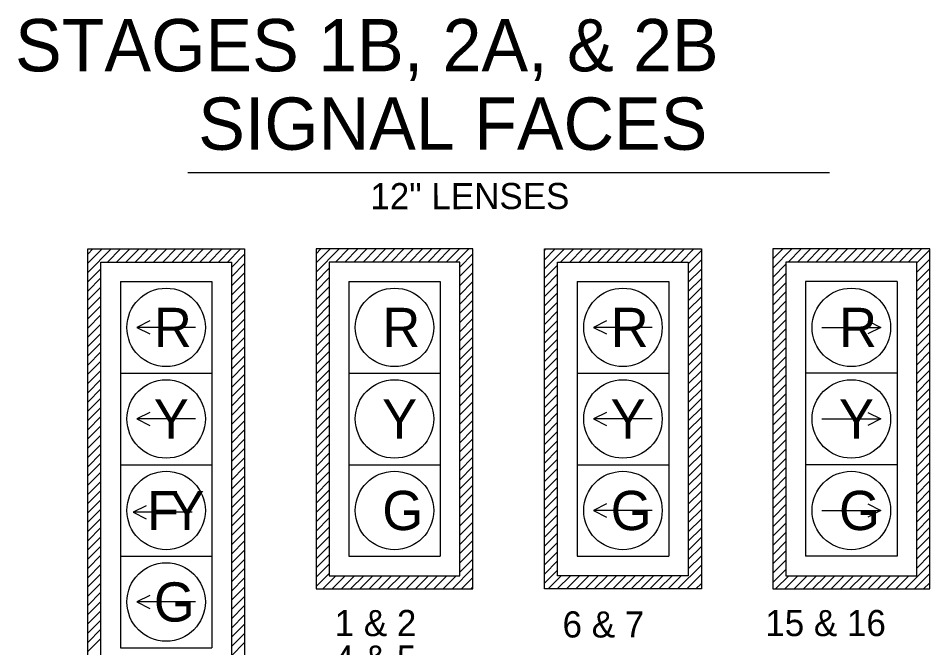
# Model space of a CAD drawing. Extents: x -218554 to 420030, y -566264 to -483460.
# Drawn here: x 419069.9 to 419209.4, y -565377 to -565280.7 of the extents above; entities that cross this region are included whole.
import ezdxf

# ---------------------------------------------------------------- set-up
doc = ezdxf.new("R2010")
doc.units = 0
doc.layers.add('T_Drafting', color=7, linetype='Continuous')
doc.layers.add('T_Notes', color=7, linetype='Continuous')

msp = doc.modelspace()

# ---------------------------------------------------------------- linework, layer by layer
at = {"layer": 'T_Drafting'}
for p, q in [((419080.56, -565381.97), (419080.56, -565315.97)), ((419080.56, -565315.97), (419104.56, -565315.97)), ((419080.56, -565319.58), (419084.16, -565315.97)), ((419080.56, -565318.16), (419082.75, -565315.97)), ((419080.56, -565316.75), (419081.33, -565315.97)), ((419083.58, -565317.97), (419085.58, -565315.97)), ((419084.99, -565317.97), (419086.99, -565315.97)), ((419086.41, -565317.97), (419088.41, -565315.97)), ((419087.82, -565317.97), (419089.82, -565315.97)), ((419089.23, -565317.97), (419091.23, -565315.97)), ((419090.65, -565317.97), (419092.65, -565315.97)), ((419092.06, -565317.97), (419094.06, -565315.97)), ((419093.48, -565317.97), (419095.48, -565315.97)), ((419094.89, -565317.97), (419096.89, -565315.97)), ((419096.3, -565317.97), (419098.3, -565315.97)), ((419097.72, -565317.97), (419099.72, -565315.97)), ((419099.13, -565317.97), (419101.13, -565315.97)), ((419100.55, -565317.97), (419102.55, -565315.97)), ((419101.96, -565317.97), (419103.96, -565315.97)), ((419104.56, -565315.97), (419104.56, -565381.97)), ((419139.49, -565315.97), (419115.49, -565315.97)), ((419115.49, -565315.97), (419115.49, -565367.97)), ((419115.49, -565319.52), (419119.04, -565315.97)), ((419115.49, -565318.1), (419117.63, -565315.97)), ((419115.49, -565316.69), (419116.21, -565315.97)), ((419118.45, -565317.97), (419120.45, -565315.97)), ((419119.87, -565317.97), (419121.87, -565315.97)), ((419121.28, -565317.97), (419123.28, -565315.97)), ((419122.7, -565317.97), (419124.7, -565315.97)), ((419124.11, -565317.97), (419126.11, -565315.97)), ((419125.53, -565317.97), (419127.53, -565315.97)), ((419126.94, -565317.97), (419128.94, -565315.97)), ((419128.35, -565317.97), (419130.35, -565315.97)), ((419129.77, -565317.97), (419131.77, -565315.97)), ((419131.18, -565317.97), (419133.18, -565315.97)), ((419132.6, -565317.97), (419134.6, -565315.97)), ((419134.01, -565317.97), (419136.01, -565315.97)), ((419135.42, -565317.97), (419137.42, -565315.97)), ((419136.84, -565317.97), (419138.84, -565315.97)), ((419139.49, -565367.97), (419139.49, -565315.97)), ((419150.43, -565315.97), (419174.43, -565315.97)), ((419150.43, -565367.97), (419150.43, -565315.97)), ((419150.43, -565319.02), (419153.48, -565315.97)), ((419150.43, -565317.61), (419152.07, -565315.97)), ((419150.43, -565316.19), (419150.65, -565315.97)), ((419152.9, -565317.97), (419154.9, -565315.97)), ((419154.31, -565317.97), (419156.31, -565315.97)), ((419155.72, -565317.97), (419157.72, -565315.97)), ((419157.14, -565317.97), (419159.14, -565315.97)), ((419158.55, -565317.97), (419160.55, -565315.97)), ((419159.97, -565317.97), (419161.97, -565315.97)), ((419161.38, -565317.97), (419163.38, -565315.97)), ((419162.79, -565317.97), (419164.79, -565315.97)), ((419164.21, -565317.97), (419166.21, -565315.97)), ((419165.62, -565317.97), (419167.62, -565315.97)), ((419167.04, -565317.97), (419169.04, -565315.97)), ((419168.45, -565317.97), (419170.45, -565315.97)), ((419169.87, -565317.97), (419171.87, -565315.97)), ((419171.28, -565317.97), (419173.28, -565315.97)), ((419174.43, -565315.97), (419174.43, -565367.97)), ((419209.37, -565315.97), (419185.37, -565315.97)), ((419185.37, -565315.97), (419185.37, -565367.97)), ((419185.37, -565318.9), (419188.29, -565315.97)), ((419185.37, -565317.48), (419186.88, -565315.97)), ((419185.37, -565316.07), (419185.47, -565315.97)), ((419187.71, -565317.97), (419189.71, -565315.97)), ((419189.12, -565317.97), (419191.12, -565315.97)), ((419190.54, -565317.97), (419192.54, -565315.97)), ((419191.95, -565317.97), (419193.95, -565315.97)), ((419193.37, -565317.97), (419195.37, -565315.97)), ((419194.78, -565317.97), (419196.78, -565315.97)), ((419196.19, -565317.97), (419198.19, -565315.97)), ((419197.61, -565317.97), (419199.61, -565315.97)), ((419199.02, -565317.97), (419201.02, -565315.97)), ((419200.44, -565317.97), (419202.44, -565315.97)), ((419201.85, -565317.97), (419203.85, -565315.97)), ((419203.27, -565317.97), (419205.27, -565315.97)), ((419204.68, -565317.97), (419206.68, -565315.97)), ((419206.09, -565317.97), (419208.09, -565315.97)), ((419207.37, -565318.11), (419209.37, -565316.11)), ((419209.37, -565367.97), (419209.37, -565315.97)), ((419102.56, -565318.79), (419104.56, -565316.79)), ((419137.49, -565318.73), (419139.49, -565316.73)), ((419172.43, -565318.23), (419174.43, -565316.23)), ((419207.37, -565319.52), (419209.37, -565317.52)), ((419102.56, -565320.21), (419104.56, -565318.21)), ((419137.49, -565320.14), (419139.49, -565318.14)), ((419150.43, -565320.43), (419152.43, -565318.43)), ((419172.43, -565319.65), (419174.43, -565317.65)), ((419185.37, -565320.31), (419187.37, -565318.31)), ((419080.56, -565320.99), (419082.56, -565318.99)), ((419102.56, -565321.62), (419104.56, -565319.62)), ((419115.49, -565320.93), (419117.49, -565318.93)), ((419137.49, -565321.56), (419139.49, -565319.56)), ((419150.43, -565321.85), (419152.43, -565319.85)), ((419172.43, -565321.06), (419174.43, -565319.06)), ((419185.37, -565321.72), (419187.37, -565319.72)), ((419207.37, -565320.94), (419209.37, -565318.94)), ((419080.56, -565322.41), (419082.56, -565320.41)), ((419085.56, -565320.97), (419099.56, -565320.97)), ((419085.56, -565320.97), (419085.56, -565334.97)), ((419099.56, -565320.97), (419099.56, -565334.97)), ((419102.56, -565323.03), (419104.56, -565321.03)), ((419115.49, -565322.35), (419117.49, -565320.35)), ((419120.49, -565320.97), (419134.49, -565320.97)), ((419120.49, -565320.97), (419120.49, -565334.97)), ((419134.49, -565320.97), (419134.49, -565334.97)), ((419137.49, -565322.97), (419139.49, -565320.97)), ((419150.43, -565323.26), (419152.43, -565321.26)), ((419155.43, -565320.97), (419169.43, -565320.97)), ((419155.43, -565320.97), (419155.43, -565334.97)), ((419169.43, -565320.97), (419169.43, -565334.97)), ((419172.43, -565322.48), (419174.43, -565320.48)), ((419185.37, -565323.14), (419187.37, -565321.14)), ((419204.37, -565320.97), (419190.37, -565320.97)), ((419190.37, -565320.97), (419190.37, -565334.97)), ((419204.37, -565320.97), (419204.37, -565334.97)), ((419207.37, -565322.35), (419209.37, -565320.35)), ((419080.56, -565323.82), (419082.56, -565321.82)), ((419102.56, -565324.45), (419104.56, -565322.45)), ((419115.49, -565323.76), (419117.49, -565321.76)), ((419137.49, -565324.39), (419139.49, -565322.39)), ((419150.43, -565324.68), (419152.43, -565322.68)), ((419172.43, -565323.89), (419174.43, -565321.89)), ((419185.37, -565324.55), (419187.37, -565322.55)), ((419207.37, -565323.77), (419209.37, -565321.77)), ((419080.56, -565325.23), (419082.56, -565323.23)), ((419102.56, -565325.86), (419104.56, -565323.86)), ((419115.49, -565325.17), (419117.49, -565323.17)), ((419137.49, -565325.8), (419139.49, -565323.8)), ((419150.43, -565326.09), (419152.43, -565324.09)), ((419172.43, -565325.3), (419174.43, -565323.3)), ((419185.37, -565325.97), (419187.37, -565323.97)), ((419207.37, -565325.18), (419209.37, -565323.18)), ((419080.56, -565326.65), (419082.56, -565324.65)), ((419102.56, -565327.28), (419104.56, -565325.28)), ((419115.49, -565326.59), (419117.49, -565324.59)), ((419137.49, -565327.22), (419139.49, -565325.22)), ((419150.43, -565327.51), (419152.43, -565325.51)), ((419172.43, -565326.72), (419174.43, -565324.72)), ((419185.37, -565327.38), (419187.37, -565325.38)), ((419207.37, -565326.59), (419209.37, -565324.59)), ((419080.56, -565328.06), (419082.56, -565326.06)), ((419102.56, -565328.69), (419104.56, -565326.69)), ((419115.49, -565328), (419117.49, -565326)), ((419137.49, -565328.63), (419139.49, -565326.63)), ((419150.43, -565328.92), (419152.43, -565326.92)), ((419172.43, -565328.13), (419174.43, -565326.13)), ((419185.37, -565328.8), (419187.37, -565326.8)), ((419207.37, -565328.01), (419209.37, -565326.01)), ((419080.56, -565329.48), (419082.56, -565327.48)), ((419097.06, -565327.97), (419088.06, -565327.97)), ((419102.56, -565330.1), (419104.56, -565328.1)), ((419115.49, -565329.42), (419117.49, -565327.42)), ((419137.49, -565330.04), (419139.49, -565328.04)), ((419150.43, -565330.33), (419152.43, -565328.33)), ((419166.93, -565327.97), (419157.93, -565327.97)), ((419172.43, -565329.55), (419174.43, -565327.55)), ((419185.37, -565330.21), (419187.37, -565328.21)), ((419192.87, -565327.97), (419201.87, -565327.97)), ((419207.37, -565329.42), (419209.37, -565327.42)), ((419080.56, -565330.89), (419082.56, -565328.89)), ((419102.56, -565331.52), (419104.56, -565329.52)), ((419115.49, -565330.83), (419117.49, -565328.83)), ((419137.49, -565331.46), (419139.49, -565329.46)), ((419150.43, -565331.75), (419152.43, -565329.75)), ((419172.43, -565330.96), (419174.43, -565328.96)), ((419185.37, -565331.62), (419187.37, -565329.62)), ((419207.37, -565330.84), (419209.37, -565328.84)), ((419080.56, -565332.31), (419082.56, -565330.31)), ((419102.56, -565332.93), (419104.56, -565330.93)), ((419115.49, -565332.25), (419117.49, -565330.25)), ((419137.49, -565332.87), (419139.49, -565330.87)), ((419150.43, -565333.16), (419152.43, -565331.16)), ((419172.43, -565332.38), (419174.43, -565330.38)), ((419185.37, -565333.04), (419187.37, -565331.04)), ((419207.37, -565332.25), (419209.37, -565330.25)), ((419080.56, -565333.72), (419082.56, -565331.72)), ((419102.56, -565334.35), (419104.56, -565332.35)), ((419115.49, -565333.66), (419117.49, -565331.66)), ((419137.49, -565334.29), (419139.49, -565332.29)), ((419150.43, -565334.58), (419152.43, -565332.58)), ((419172.43, -565333.79), (419174.43, -565331.79)), ((419185.37, -565334.45), (419187.37, -565332.45)), ((419207.37, -565333.67), (419209.37, -565331.67)), ((419080.56, -565335.13), (419082.56, -565333.13)), ((419102.56, -565335.76), (419104.56, -565333.76)), ((419115.49, -565335.07), (419117.49, -565333.07)), ((419137.49, -565335.7), (419139.49, -565333.7)), ((419150.43, -565335.99), (419152.43, -565333.99)), ((419172.43, -565335.2), (419174.43, -565333.2)), ((419185.37, -565335.87), (419187.37, -565333.87)), ((419207.37, -565335.08), (419209.37, -565333.08)), ((419080.56, -565336.55), (419082.56, -565334.55)), ((419085.56, -565334.97), (419099.56, -565334.97)), ((419085.56, -565334.97), (419085.56, -565348.97)), ((419099.56, -565334.97), (419099.56, -565348.97)), ((419102.56, -565337.18), (419104.56, -565335.18)), ((419115.49, -565336.49), (419117.49, -565334.49)), ((419120.49, -565334.97), (419134.49, -565334.97)), ((419120.49, -565334.97), (419120.49, -565348.97)), ((419134.49, -565334.97), (419134.49, -565348.97)), ((419137.49, -565337.12), (419139.49, -565335.12)), ((419150.43, -565337.41), (419152.43, -565335.41)), ((419155.43, -565334.97), (419169.43, -565334.97)), ((419155.43, -565334.97), (419155.43, -565348.97)), ((419169.43, -565334.97), (419169.43, -565348.97)), ((419172.43, -565336.62), (419174.43, -565334.62)), ((419185.37, -565337.28), (419187.37, -565335.28)), ((419204.37, -565334.97), (419190.37, -565334.97)), ((419190.37, -565334.97), (419190.37, -565348.97)), ((419204.37, -565334.97), (419204.37, -565348.97)), ((419207.37, -565336.49), (419209.37, -565334.49)), ((419080.56, -565337.96), (419082.56, -565335.96)), ((419102.56, -565338.59), (419104.56, -565336.59)), ((419115.49, -565337.9), (419117.49, -565335.9)), ((419137.49, -565338.53), (419139.49, -565336.53)), ((419150.43, -565338.82), (419152.43, -565336.82)), ((419172.43, -565338.03), (419174.43, -565336.03)), ((419185.37, -565338.69), (419187.37, -565336.69)), ((419207.37, -565337.91), (419209.37, -565335.91)), ((419080.56, -565339.38), (419082.56, -565337.38)), ((419102.56, -565340), (419104.56, -565338)), ((419115.49, -565339.32), (419117.49, -565337.32)), ((419137.49, -565339.94), (419139.49, -565337.94)), ((419150.43, -565340.23), (419152.43, -565338.23)), ((419172.43, -565339.45), (419174.43, -565337.45)), ((419185.37, -565340.11), (419187.37, -565338.11)), ((419207.37, -565339.32), (419209.37, -565337.32)), ((419080.56, -565340.79), (419082.56, -565338.79)), ((419102.56, -565341.42), (419104.56, -565339.42)), ((419115.49, -565340.73), (419117.49, -565338.73)), ((419137.49, -565341.36), (419139.49, -565339.36)), ((419150.43, -565341.65), (419152.43, -565339.65)), ((419172.43, -565340.86), (419174.43, -565338.86)), ((419185.37, -565341.52), (419187.37, -565339.52)), ((419207.37, -565340.74), (419209.37, -565338.74)), ((419080.56, -565342.21), (419082.56, -565340.21)), ((419102.56, -565342.83), (419104.56, -565340.83)), ((419115.49, -565342.14), (419117.49, -565340.14)), ((419137.49, -565342.77), (419139.49, -565340.77)), ((419150.43, -565343.06), (419152.43, -565341.06)), ((419172.43, -565342.28), (419174.43, -565340.28)), ((419185.37, -565342.94), (419187.37, -565340.94)), ((419207.37, -565342.15), (419209.37, -565340.15)), ((419080.56, -565343.62), (419082.56, -565341.62)), ((419097.06, -565341.97), (419088.06, -565341.97)), ((419102.56, -565344.25), (419104.56, -565342.25)), ((419115.49, -565343.56), (419117.49, -565341.56)), ((419137.49, -565344.19), (419139.49, -565342.19)), ((419150.43, -565344.48), (419152.43, -565342.48)), ((419166.93, -565341.97), (419157.93, -565341.97)), ((419172.43, -565343.69), (419174.43, -565341.69)), ((419185.37, -565344.35), (419187.37, -565342.35)), ((419192.87, -565341.97), (419201.87, -565341.97)), ((419207.37, -565343.57), (419209.37, -565341.57)), ((419080.56, -565345.03), (419082.56, -565343.03)), ((419102.56, -565345.66), (419104.56, -565343.66)), ((419115.49, -565344.97), (419117.49, -565342.97)), ((419137.49, -565345.6), (419139.49, -565343.6)), ((419150.43, -565345.89), (419152.43, -565343.89)), ((419172.43, -565345.1), (419174.43, -565343.1)), ((419185.37, -565345.77), (419187.37, -565343.77)), ((419207.37, -565344.98), (419209.37, -565342.98)), ((419080.56, -565346.45), (419082.56, -565344.45)), ((419102.56, -565347.08), (419104.56, -565345.08)), ((419115.49, -565346.39), (419117.49, -565344.39)), ((419137.49, -565347.01), (419139.49, -565345.01)), ((419150.43, -565347.3), (419152.43, -565345.3)), ((419172.43, -565346.52), (419174.43, -565344.52)), ((419185.37, -565347.18), (419187.37, -565345.18)), ((419207.37, -565346.39), (419209.37, -565344.39)), ((419080.56, -565347.86), (419082.56, -565345.86)), ((419102.56, -565348.49), (419104.56, -565346.49)), ((419115.49, -565347.8), (419117.49, -565345.8)), ((419137.49, -565348.43), (419139.49, -565346.43)), ((419150.43, -565348.72), (419152.43, -565346.72)), ((419172.43, -565347.93), (419174.43, -565345.93)), ((419185.37, -565348.59), (419187.37, -565346.59)), ((419207.37, -565347.81), (419209.37, -565345.81)), ((419080.56, -565349.28), (419082.56, -565347.28)), ((419102.56, -565349.9), (419104.56, -565347.9)), ((419115.49, -565349.22), (419117.49, -565347.22)), ((419137.49, -565349.84), (419139.49, -565347.84)), ((419150.43, -565350.13), (419152.43, -565348.13)), ((419172.43, -565349.35), (419174.43, -565347.35)), ((419185.37, -565350.01), (419187.37, -565348.01)), ((419207.37, -565349.22), (419209.37, -565347.22)), ((419080.56, -565350.69), (419082.56, -565348.69)), ((419085.56, -565348.97), (419099.56, -565348.97)), ((419085.56, -565348.97), (419085.56, -565362.97)), ((419099.56, -565348.97), (419099.56, -565362.97)), ((419102.56, -565351.32), (419104.56, -565349.32)), ((419115.49, -565350.63), (419117.49, -565348.63)), ((419120.49, -565348.97), (419134.49, -565348.97)), ((419120.49, -565348.97), (419120.49, -565362.97)), ((419134.49, -565348.97), (419134.49, -565362.97)), ((419137.49, -565351.26), (419139.49, -565349.26)), ((419150.43, -565351.55), (419152.43, -565349.55)), ((419155.43, -565348.97), (419169.43, -565348.97)), ((419155.43, -565348.97), (419155.43, -565362.97)), ((419169.43, -565348.97), (419169.43, -565362.97)), ((419172.43, -565350.76), (419174.43, -565348.76)), ((419185.37, -565351.42), (419187.37, -565349.42)), ((419204.37, -565348.97), (419190.37, -565348.97)), ((419190.37, -565348.97), (419190.37, -565362.97)), ((419204.37, -565348.97), (419204.37, -565362.97)), ((419207.37, -565350.64), (419209.37, -565348.64)), ((419080.56, -565352.1), (419082.56, -565350.1)), ((419102.56, -565352.73), (419104.56, -565350.73)), ((419115.49, -565352.04), (419117.49, -565350.04)), ((419137.49, -565352.67), (419139.49, -565350.67)), ((419150.43, -565352.96), (419152.43, -565350.96)), ((419172.43, -565352.17), (419174.43, -565350.17)), ((419185.37, -565352.84), (419187.37, -565350.84)), ((419207.37, -565352.05), (419209.37, -565350.05)), ((419080.56, -565353.52), (419082.56, -565351.52)), ((419102.56, -565354.15), (419104.56, -565352.15)), ((419115.49, -565353.46), (419117.49, -565351.46)), ((419137.49, -565354.09), (419139.49, -565352.09)), ((419150.43, -565354.38), (419152.43, -565352.38)), ((419172.43, -565353.59), (419174.43, -565351.59)), ((419185.37, -565354.25), (419187.37, -565352.25)), ((419207.37, -565353.46), (419209.37, -565351.46)), ((419080.56, -565354.93), (419082.56, -565352.93)), ((419102.56, -565355.56), (419104.56, -565353.56)), ((419115.49, -565354.87), (419117.49, -565352.87)), ((419137.49, -565355.5), (419139.49, -565353.5)), ((419172.43, -565355), (419174.43, -565353)), ((419185.37, -565355.67), (419187.37, -565353.67)), ((419207.37, -565354.88), (419209.37, -565352.88)), ((419080.56, -565356.35), (419082.56, -565354.35)), ((419102.56, -565356.97), (419104.56, -565354.97)), ((419115.49, -565356.29), (419117.49, -565354.29)), ((419137.49, -565356.91), (419139.49, -565354.91)), ((419150.43, -565355.79), (419152.43, -565353.79)), ((419172.43, -565356.42), (419174.43, -565354.42)), ((419185.37, -565357.08), (419187.37, -565355.08)), ((419207.37, -565356.29), (419209.37, -565354.29)), ((419080.56, -565357.76), (419082.56, -565355.76)), ((419096.53, -565356.25), (419087.53, -565356.25)), ((419102.56, -565358.39), (419104.56, -565356.39)), ((419115.49, -565357.7), (419117.49, -565355.7)), ((419137.49, -565358.33), (419139.49, -565356.33)), ((419150.43, -565357.2), (419152.43, -565355.2)), ((419166.93, -565355.97), (419157.93, -565355.97)), ((419172.43, -565357.83), (419174.43, -565355.83)), ((419185.37, -565358.49), (419187.37, -565356.49)), ((419192.87, -565355.97), (419201.87, -565355.97)), ((419207.37, -565357.71), (419209.37, -565355.71)), ((419080.56, -565359.18), (419082.56, -565357.18)), ((419102.56, -565359.8), (419104.56, -565357.8)), ((419115.49, -565359.12), (419117.49, -565357.12)), ((419137.49, -565359.74), (419139.49, -565357.74)), ((419150.43, -565358.62), (419152.43, -565356.62)), ((419172.43, -565359.25), (419174.43, -565357.25)), ((419185.37, -565359.91), (419187.37, -565357.91)), ((419207.37, -565359.12), (419209.37, -565357.12)), ((419080.56, -565360.59), (419082.56, -565358.59)), ((419102.56, -565361.22), (419104.56, -565359.22)), ((419115.49, -565360.53), (419117.49, -565358.53)), ((419137.49, -565361.16), (419139.49, -565359.16)), ((419150.43, -565360.03), (419152.43, -565358.03)), ((419172.43, -565360.66), (419174.43, -565358.66)), ((419185.37, -565361.32), (419187.37, -565359.32)), ((419207.37, -565360.54), (419209.37, -565358.54)), ((419080.56, -565362), (419082.56, -565360)), ((419102.56, -565362.63), (419104.56, -565360.63)), ((419115.49, -565361.94), (419117.49, -565359.94)), ((419137.49, -565362.57), (419139.49, -565360.57)), ((419150.43, -565361.45), (419152.43, -565359.45)), ((419172.43, -565362.07), (419174.43, -565360.07)), ((419185.37, -565362.74), (419187.37, -565360.74)), ((419207.37, -565361.95), (419209.37, -565359.95)), ((419080.56, -565363.42), (419082.56, -565361.42)), ((419102.56, -565364.05), (419104.56, -565362.05)), ((419115.49, -565363.36), (419117.49, -565361.36)), ((419137.49, -565363.99), (419139.49, -565361.99)), ((419150.43, -565362.86), (419152.43, -565360.86)), ((419172.43, -565363.49), (419174.43, -565361.49)), ((419185.37, -565364.15), (419187.37, -565362.15)), ((419207.37, -565363.36), (419209.37, -565361.36)), ((419080.56, -565364.83), (419082.56, -565362.83)), ((419085.56, -565362.97), (419099.56, -565362.97)), ((419085.56, -565362.97), (419085.56, -565376.97)), ((419099.56, -565362.97), (419099.56, -565376.97)), ((419102.56, -565365.46), (419104.56, -565363.46)), ((419115.49, -565364.77), (419117.49, -565362.77)), ((419120.49, -565362.97), (419134.49, -565362.97)), ((419137.49, -565365.4), (419139.49, -565363.4)), ((419150.43, -565364.28), (419152.43, -565362.28)), ((419155.43, -565362.97), (419169.43, -565362.97)), ((419172.43, -565364.9), (419174.43, -565362.9)), ((419204.37, -565362.97), (419190.37, -565362.97)), ((419207.37, -565364.78), (419209.37, -565362.78)), ((419080.56, -565366.25), (419082.56, -565364.25)), ((419102.56, -565366.87), (419104.56, -565364.87)), ((419115.49, -565366.19), (419117.49, -565364.19)), ((419136.34, -565367.97), (419139.49, -565364.81)), ((419150.43, -565365.69), (419152.43, -565363.69)), ((419170.78, -565367.97), (419174.43, -565364.32)), ((419185.37, -565365.57), (419187.37, -565363.57)), ((419205.59, -565367.97), (419209.37, -565364.19)), ((419080.56, -565367.66), (419082.56, -565365.66)), ((419102.56, -565368.29), (419104.56, -565366.29)), ((419115.49, -565367.6), (419117.49, -565365.6)), ((419116.54, -565367.97), (419118.54, -565365.97)), ((419117.95, -565367.97), (419119.95, -565365.97)), ((419119.37, -565367.97), (419121.37, -565365.97)), ((419120.78, -565367.97), (419122.78, -565365.97)), ((419122.19, -565367.97), (419124.19, -565365.97)), ((419123.61, -565367.97), (419125.61, -565365.97)), ((419125.02, -565367.97), (419127.02, -565365.97)), ((419126.44, -565367.97), (419128.44, -565365.97)), ((419127.85, -565367.97), (419129.85, -565365.97)), ((419129.27, -565367.97), (419131.27, -565365.97)), ((419130.68, -565367.97), (419132.68, -565365.97)), ((419132.09, -565367.97), (419134.09, -565365.97)), ((419133.51, -565367.97), (419135.51, -565365.97)), ((419134.92, -565367.97), (419136.92, -565365.97)), ((419137.75, -565367.97), (419139.49, -565366.23)), ((419150.43, -565367.1), (419152.43, -565365.1)), ((419150.98, -565367.97), (419152.98, -565365.97)), ((419152.39, -565367.97), (419154.39, -565365.97)), ((419153.81, -565367.97), (419155.81, -565365.97)), ((419155.22, -565367.97), (419157.22, -565365.97)), ((419156.64, -565367.97), (419158.64, -565365.97)), ((419158.05, -565367.97), (419160.05, -565365.97)), ((419159.46, -565367.97), (419161.46, -565365.97)), ((419160.88, -565367.97), (419162.88, -565365.97)), ((419162.29, -565367.97), (419164.29, -565365.97)), ((419163.71, -565367.97), (419165.71, -565365.97)), ((419165.12, -565367.97), (419167.12, -565365.97)), ((419166.53, -565367.97), (419168.53, -565365.97)), ((419167.95, -565367.97), (419169.95, -565365.97)), ((419169.36, -565367.97), (419171.36, -565365.97)), ((419172.19, -565367.97), (419174.43, -565365.73)), ((419185.37, -565366.98), (419187.37, -565364.98)), ((419185.79, -565367.97), (419187.79, -565365.97)), ((419187.21, -565367.97), (419189.21, -565365.97)), ((419188.62, -565367.97), (419190.62, -565365.97)), ((419190.03, -565367.97), (419192.03, -565365.97)), ((419191.45, -565367.97), (419193.45, -565365.97)), ((419192.86, -565367.97), (419194.86, -565365.97)), ((419194.28, -565367.97), (419196.28, -565365.97)), ((419195.69, -565367.97), (419197.69, -565365.97)), ((419197.11, -565367.97), (419199.11, -565365.97)), ((419198.52, -565367.97), (419200.52, -565365.97)), ((419199.93, -565367.97), (419201.93, -565365.97)), ((419201.35, -565367.97), (419203.35, -565365.97)), ((419202.76, -565367.97), (419204.76, -565365.97)), ((419204.18, -565367.97), (419206.18, -565365.97)), ((419207.01, -565367.97), (419209.37, -565365.61)), ((419080.56, -565369.08), (419082.56, -565367.08)), ((419102.56, -565369.7), (419104.56, -565367.7)), ((419139.17, -565367.97), (419139.49, -565367.64)), ((419173.61, -565367.97), (419174.43, -565367.15)), ((419208.42, -565367.97), (419209.37, -565367.02)), ((419080.56, -565370.49), (419082.56, -565368.49)), ((419102.56, -565371.12), (419104.56, -565369.12)), ((419115.49, -565367.97), (419139.49, -565367.97)), ((419174.43, -565367.97), (419150.43, -565367.97)), ((419185.37, -565367.97), (419209.37, -565367.97)), ((419080.56, -565371.9), (419082.56, -565369.9)), ((419097.06, -565369.97), (419088.06, -565369.97)), ((419080.56, -565373.32), (419082.56, -565371.32)), ((419102.56, -565372.53), (419104.56, -565370.53)), ((419080.56, -565374.73), (419082.56, -565372.73)), ((419102.56, -565373.95), (419104.56, -565371.95)), ((419080.56, -565376.15), (419082.56, -565374.15)), ((419102.56, -565375.36), (419104.56, -565373.36)), ((419080.56, -565377.56), (419082.56, -565375.56)), ((419102.56, -565376.77), (419104.56, -565374.77)), ((419085.56, -565376.97), (419099.56, -565376.97)), ((419102.56, -565378.19), (419104.56, -565376.19))]:
    msp.add_line(p, q, dxfattribs=at)
for points in [[(419082.56, -565379.97), (419082.56, -565317.97), (419102.56, -565317.97), (419102.56, -565379.97)], [(419137.49, -565365.97), (419137.49, -565317.97), (419117.49, -565317.97), (419117.49, -565365.97)], [(419152.43, -565317.97), (419172.43, -565317.97), (419172.43, -565365.97), (419152.43, -565365.97)], [(419207.37, -565317.97), (419187.37, -565317.97), (419187.37, -565365.97), (419207.37, -565365.97)]]:
    msp.add_lwpolyline(points, close=True, dxfattribs=at)
for points in [[(419090.06, -565326.97), (419088.06, -565327.97), (419090.06, -565328.97)], [(419159.93, -565326.97), (419157.93, -565327.97), (419159.93, -565328.97)], [(419199.87, -565326.97), (419201.87, -565327.97), (419199.87, -565328.97)], [(419090.06, -565340.97), (419088.06, -565341.97), (419090.06, -565342.97)], [(419159.93, -565340.97), (419157.93, -565341.97), (419159.93, -565342.97)], [(419199.87, -565340.97), (419201.87, -565341.97), (419199.87, -565342.97)], [(419159.93, -565354.97), (419157.93, -565355.97), (419159.93, -565356.97)], [(419199.87, -565354.97), (419201.87, -565355.97), (419199.87, -565356.97)], [(419089.53, -565355.25), (419087.53, -565356.25), (419089.53, -565357.25)], [(419090.06, -565368.97), (419088.06, -565369.97), (419090.06, -565370.97)]]:
    msp.add_lwpolyline(points, dxfattribs=at)
for centre in [(419092.56, -565327.97), (419127.49, -565327.97), (419162.43, -565327.97), (419197.37, -565327.97), (419092.56, -565341.97), (419127.49, -565341.97), (419162.43, -565341.97), (419197.37, -565341.97), (419092.56, -565355.97), (419127.49, -565355.97), (419162.43, -565355.97), (419197.37, -565355.97), (419092.56, -565369.97)]:
    msp.add_circle(centre, 6, dxfattribs=at)
at = {"layer": 'T_Notes'}
msp.add_line((419095.87, -565304.27), (419194.05, -565304.27), dxfattribs=at)

# ---------------------------------------------------------------- texts
at = {"layer": 'T_Drafting'}
msp.add_text('12" LENSES', height=4, rotation=0.072, dxfattribs=at).set_placement((419123.8, -565309.9))
for s, p in [('R', (419090.69, -565330.97)), ('R', (419125.63, -565330.97)), ('R', (419160.57, -565330.97)), ('R', (419195.5, -565330.97)), ('Y', (419090.67, -565344.97)), ('Y', (419125.6, -565344.97)), ('Y', (419160.54, -565344.97)), ('Y', (419195.48, -565344.97)), ('F', (419089.65, -565358.97)), ('Y', (419093.08, -565358.97)), ('G', (419125.63, -565358.97)), ('G', (419160.57, -565358.97)), ('G', (419195.5, -565358.97)), ('G', (419090.69, -565372.97))]:
    msp.add_text(s, height=6, dxfattribs=at).set_placement(p)
at = {"layer": 'T_Notes'}
for s, p in [('STAGES 1B, 2A, & 2B', (419069.45, -565288.8)), ('SIGNAL FACES', (419097.47, -565300.8))]:
    msp.add_text(s, height=8, rotation=360, dxfattribs=at).set_placement(p)
for s, p in [('1 & 2', (419118.34, -565375.19)), ('6 & 7', (419153.2, -565375.4)), ('15 & 16', (419184.21, -565375.19)), ('4 & 5', (419118.34, -565380.61))]:
    msp.add_text(s, height=4, dxfattribs=at).set_placement(p)

doc.saveas('drawing.dxf')
